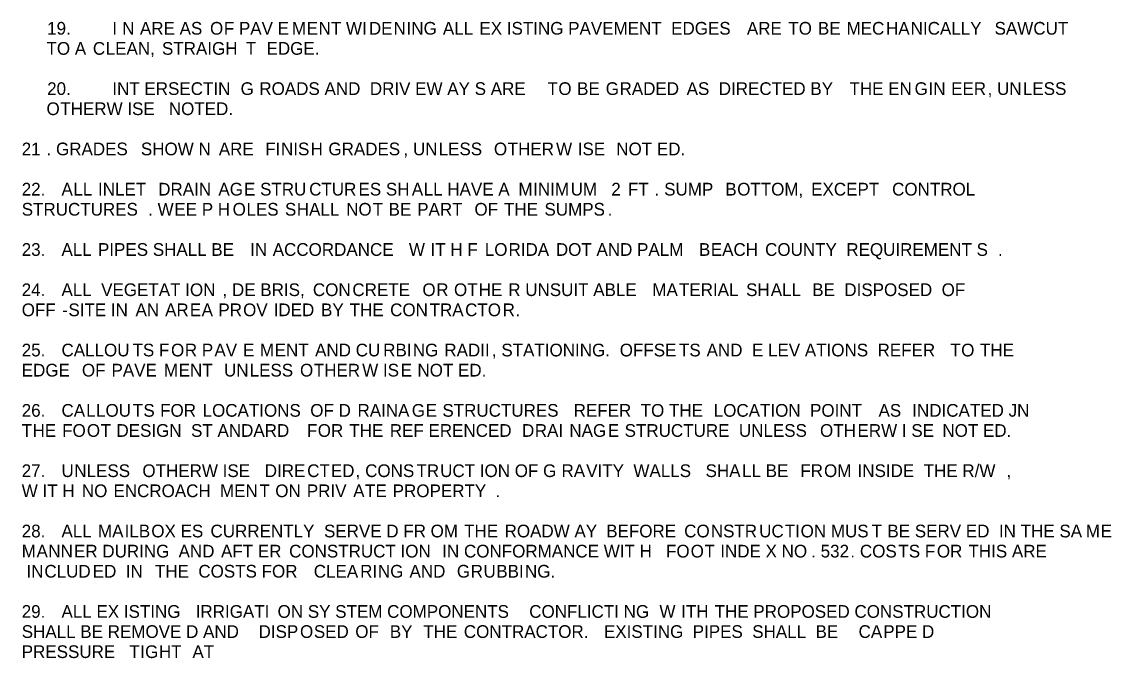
# Model space of a CAD drawing. Extents: x 783907 to 784590, y 832310 to 832609.
# Drawn here: x 783907.3 to 783958.7, y 832340.8 to 832370.9 of the extents above; entities that cross this region are included whole.
import ezdxf

# ---------------------------------------------------------------- set-up
doc = ezdxf.new("R2010")
doc.units = 0
doc.layers.add('Miscellaneous0', color=7, linetype='Continuous')

msp = doc.modelspace()

# ---------------------------------------------------------------- texts
at = {"layer": 'Miscellaneous0'}
for s, p in [('19.', (783908.482, 832370.257)), ('I ', (783911.559, 832370.257)), ('N ', (783912.024, 832370.257)), ('ARE AS ', (783912.863, 832370.257)), ('O', (783916.171, 832370.257)), ('F PAV E', (783916.823, 832370.257)), ('M', (783920.038, 832370.257)), ('E', (783920.736, 832370.257)), ('NT WI', (783921.296, 832370.257)), ('DE', (783923.67, 832370.257)), ('N', (783924.835, 832370.257)), ('I', (783925.44, 832370.257)), ('NG ', (783925.673, 832370.257)), ('ALL ', (783927.163, 832370.257)), ('EX ISTING PAVEMENT  EDGES ', (783928.887, 832370.257)), ('ARE ', (783941.513, 832370.257)), ('TO ', (783943.469, 832370.257)), ('BE ', (783944.867, 832370.257)), ('MEC', (783946.218, 832370.257)), ('HA', (783948.081, 832370.257)), ('NICALLY  ', (783949.246, 832370.257)), ('SAWCUT ', (783953.206, 832370.257)), ('TO A ', (783908.452, 832369.307)), ('C', (783910.641, 832369.307)), ('LEAN, ', (783911.246, 832369.307)), ('STRAIGH ', (783913.902, 832369.307)), ('T  ', (783917.861, 832369.307)), ('EDGE.', (783918.839, 832369.307)), ('20.', (783908.482, 832367.407)), ('INT ERSECTIN ', (783911.559, 832367.407)), ('G ', (783917.614, 832367.407)), ('ROADS AND  DRIV EW AY S ARE  ', (783918.499, 832367.407)), ('T', (783932.101, 832367.407)), ('O ', (783932.614, 832367.407)), ('BE ', (783933.499, 832367.407)), ('G', (783934.85, 832367.407)), ('RADED ', (783935.502, 832367.407)), ('AS  DIRECTED BY  ', (783938.67, 832367.407)), ('THE EN', (783946.357, 832367.407)), ('G', (783949.431, 832367.407)), ('I', (783950.083, 832367.407)), ('N ', (783950.316, 832367.407)), ('EER', (783951.154, 832367.407)), (' UN', (783953.1, 832367.407)), ('LESS ', (783954.543, 832367.407)), ('O', (783908.452, 832366.457)), ('THERW ISE  ', (783909.104, 832366.457)), ('NOTED.', (783914.227, 832366.457)), (',', (783952.878, 832367.407)), ('21 ', (783907.282, 832364.557)), ('GRADES  ', (783908.901, 832364.557)), ('SHOW N ', (783912.907, 832364.557)), ('ARE  ', (783916.586, 832364.557)), ('FI', (783918.776, 832364.557)), ('NIS', (783919.521, 832364.557)), ('H ', (783920.918, 832364.557)), ('GRADES', (783921.757, 832364.557)), ('UN', (783925.752, 832364.557)), ('LESS  ', (783926.963, 832364.557)), ('O', (783929.572, 832364.557)), ('THER', (783930.224, 832364.557)), ('W ', (783932.507, 832364.557)), ('ISE  ', (783933.531, 832364.557)), ('NOT ED.', (783935.348, 832364.557)), ('.', (783908.446, 832364.557)), (',', (783925.298, 832364.557)), ('22.', (783907.282, 832362.657)), ('A', (783909.159, 832362.657)), ('LL ', (783909.718, 832362.657)), ('INLET  ', (783910.883, 832362.657)), ('DRAIN ', (783913.724, 832362.657)), ('AG', (783916.566, 832362.657)), ('E STRU', (783917.777, 832362.657)), ('CTUR', (783920.851, 832362.657)), ('ES SH', (783923.18, 832362.657)), ('A', (783925.696, 832362.657)), ('LL HAVE A ', (783926.256, 832362.657)), ('M', (783930.729, 832362.657)), ('INIM', (783931.427, 832362.657)), ('UM   2 ', (783933.196, 832362.657)), ('FT ', (783935.897, 832362.657)), ('SUMP  ', (783937.609, 832362.657)), ('B', (783940.497, 832362.657)), ('OTTOM, ', (783941.056, 832362.657)), ('EXCEPT  ', (783944.548, 832362.657)), ('CONTROL ', (783948.369, 832362.657)), ('.', (783937.154, 832362.657)), ('STRUCTURES ', (783907.282, 832361.707)), ('W', (783913.698, 832361.707)), ('EE P H', (783914.489, 832361.707)), ('O', (783917.238, 832361.707)), ('LES ', (783917.891, 832361.707)), ('S', (783919.708, 832361.707)), ('HALL ', (783920.267, 832361.707)), ('NO', (783922.597, 832361.707)), ('T ', (783923.854, 832361.707)), ('BE ', (783924.599, 832361.707)), ('PART  ', (783925.951, 832361.707)), ('OF ', (783928.653, 832361.707)), ('THE ', (783930.05, 832361.707)), ('SUMPS', (783931.959, 832361.707)), ('.', (783913.244, 832361.707)), ('.', (783934.941, 832361.707)), ('23.', (783907.282, 832359.807)), ('ALL ', (783909.159, 832359.807)), ('PIPES SHALL BE  ', (783910.883, 832359.807)), ('I', (783918.059, 832359.807)), ('N ', (783918.291, 832359.807)), ('ACCORDANCE  ', (783919.13, 832359.807)), ('W ', (783925.558, 832359.807)), ('IT H F ', (783926.582, 832359.807)), ('LO', (783929.143, 832359.807)), ('RIDA ', (783930.261, 832359.807)), ('DOT AND PALM  ', (783932.497, 832359.807)), ('B', (783939.251, 832359.807)), ('EACH ', (783939.81, 832359.807)), ('COUNTY  REQUIREMENT S', (783942.373, 832359.807)), ('.', (783953.366, 832359.807)), ('24.', (783907.282, 832357.907)), ('ALL  VEGETAT ION', (783909.159, 832357.907)), ('DE BRIS, ', (783917.207, 832357.907)), ('CON', (783921.027, 832357.907)), ('CRETE  ', (783922.89, 832357.907)), ('O', (783926.197, 832357.907)), ('R ', (783926.849, 832357.907)), ('OT', (783927.688, 832357.907)), ('HE ', (783928.852, 832357.907)), ('R UNSUIT ABLE  ', (783930.249, 832357.907)), ('MA', (783937.051, 832357.907)), ('TERIAL ', (783938.308, 832357.907)), ('SH', (783941.476, 832357.907)), ('ALL  ', (783942.641, 832357.907)), ('BE  DISPOSED  OF  ', (783944.598, 832357.907)), (',', (783916.753, 832357.907)), ('OFF ', (783907.282, 832356.957)), ('SITE IN ', (783909.486, 832356.957)), ('AN ', (783912.654, 832356.957)), ('AR', (783914.051, 832356.957)), ('E', (783915.216, 832356.957)), ('A ', (783915.775, 832356.957)), ('PR', (783916.567, 832356.957)), ('OV ', (783917.732, 832356.957)), ('IDED ', (783919.176, 832356.957)), ('BY ', (783921.412, 832356.957)), ('THE ', (783922.763, 832356.957)), ('CON', (783924.673, 832356.957)), ('TRA', (783926.536, 832356.957)), ('CTO', (783928.213, 832356.957)), ('R', (783929.983, 832356.957)), ('-', (783909.191, 832356.957)), ('.', (783930.589, 832356.957)), ('25.', (783907.282, 832355.057)), ('CALLOU', (783909.159, 832355.057)), ('TS F', (783912.513, 832355.057)), ('O', (783914.33, 832355.057)), ('R P', (783914.982, 832355.057)), ('AV ', (783916.379, 832355.057)), ('E ', (783917.731, 832355.057)), ('M', (783918.523, 832355.057)), ('ENT ', (783919.221, 832355.057)), ('AND CU', (783921.131, 832355.057)), ('RBI', (783924.345, 832355.057)), ('NG ', (783925.742, 832355.057)), ('RADII', (783927.233, 832355.057)), ('STATIONING. ', (783929.923, 832355.057)), ('OFFSE', (783935.512, 832355.057)), ('TS ', (783938.307, 832355.057)), ('AND  E LEV ATIONS  REFER ', (783939.612, 832355.057)), ('T', (783951.118, 832355.057)), ('O ', (783951.63, 832355.057)), ('THE ', (783952.515, 832355.057)), ('EDGE  ', (783907.282, 832354.107)), ('OF ', (783910.123, 832354.107)), ('PAVE ', (783911.521, 832354.107)), ('M', (783913.991, 832354.107)), ('ENT  ', (783914.689, 832354.107)), ('UN', (783916.831, 832354.107)), ('LESS ', (783918.042, 832354.107)), ('O', (783920.419, 832354.107)), ('THER', (783921.071, 832354.107)), ('W IS', (783923.354, 832354.107)), ('E ', (783925.17, 832354.107)), ('NOT ED.', (783925.962, 832354.107)), (',', (783929.469, 832355.057)), ('26.', (783907.282, 832352.207)), ('CA', (783909.159, 832352.207)), ('L', (783910.324, 832352.207)), ('LOU', (783910.79, 832352.207)), ('T', (783912.513, 832352.207)), ('S ', (783913.025, 832352.207)), ('FOR ', (783913.817, 832352.207)), ('LOCATIONS  OF D', (783915.82, 832352.207)), ('RAINA', (783923.133, 832352.207)), ('G', (783925.695, 832352.207)), ('E ', (783926.348, 832352.207)), ('STRUCTURES  ', (783927.14, 832352.207)), ('REFER  TO THE ', (783933.335, 832352.207)), ('LOCATION  POINT  ', (783939.949, 832352.207)), ('AS  ', (783947.728, 832352.207)), ('I', (783949.312, 832352.207)), ('NDICATED JN ', (783949.544, 832352.207)), ('T', (783907.282, 832351.257)), ('HE ', (783907.794, 832351.257)), ('FO', (783909.191, 832351.257)), ('O', (783910.356, 832351.257)), ('T ', (783911.008, 832351.257)), ('DESIGN  ST ANDARD  ', (783911.753, 832351.257)), ('F', (783920.743, 832351.257)), ('OR ', (783921.255, 832351.257)), ('THE ', (783922.746, 832351.257)), ('REF ERENCED ', (783924.656, 832351.257)), ('D', (783930.898, 832351.257)), ('RAI ', (783931.503, 832351.257)), ('NAG', (783933.134, 832351.257)), ('E ', (783934.951, 832351.257)), ('STRUCTURE  UNLESS ', (783935.743, 832351.257)), ('OTH', (783944.966, 832351.257)), ('ERW I SE ', (783946.736, 832351.257)), ('NOT ED.', (783950.742, 832351.257)), ('27.', (783907.282, 832349.357)), ('U', (783909.159, 832349.357)), ('NLESS  ', (783909.764, 832349.357)), ('OTHERW ISE  ', (783912.979, 832349.357)), ('DIRE', (783918.755, 832349.357)), ('CT', (783920.758, 832349.357)), ('ED', (783921.875, 832349.357)), ('CONS', (783923.494, 832349.357)), ('TR', (783925.917, 832349.357)), ('UCT ION OF G', (783927.034, 832349.357)), ('RA', (783932.763, 832349.357)), ('VITY  WALLS  ', (783933.928, 832349.357)), ('SHA', (783939.564, 832349.357)), ('LL BE  ', (783941.288, 832349.357)), ('FR', (783944.037, 832349.357)), ('OM ', (783945.155, 832349.357)), ('INSIDE  THE R/W ', (783946.738, 832349.357)), ('W IT H ', (783907.282, 832348.407)), ('NO ', (783910.122, 832348.407)), ('ENCROACH ', (783911.612, 832348.407)), ('MEN', (783916.643, 832348.407)), ('T ', (783918.506, 832348.407)), ('ON ', (783919.251, 832348.407)), ('PRIV ', (783920.741, 832348.407)), ('A', (783922.931, 832348.407)), (',', (783923.04, 832349.357)), ('TE ', (783923.49, 832348.407)), ('PROPERTY ', (783924.795, 832348.407)), (',', (783953.771, 832349.357)), ('.', (783929.64, 832348.407)), ('28.', (783907.282, 832346.507)), ('ALL ', (783909.159, 832346.507)), ('MA', (783910.883, 832346.507)), ('ILB', (783912.141, 832346.507)), ('OX ES ', (783913.399, 832346.507)), ('CURRENTLY ', (783916.194, 832346.507)), ('SERVE D FR', (783921.551, 832346.507)), ('OM ', (783926.583, 832346.507)), ('THE ', (783928.166, 832346.507)), ('ROADW AY ', (783930.076, 832346.507)), ('BEFORE ', (783934.873, 832346.507)), ('CO', (783938.554, 832346.507)), ('NSTR', (783939.811, 832346.507)), ('UC', (783942.094, 832346.507)), ('TI', (783943.305, 832346.507)), ('ON MUS', (783944.05, 832346.507)), ('T ', (783947.403, 832346.507)), ('BE SERV ED ', (783948.148, 832346.507)), ('IN THE SA', (783953.413, 832346.507)), ('M', (783957.513, 832346.507)), ('E ', (783958.211, 832346.507)), ('M', (783907.282, 832345.557)), ('A', (783907.98, 832345.557)), ('NN', (783908.539, 832345.557)), ('ER DURING ', (783909.75, 832345.557)), ('AND ', (783914.687, 832345.557)), ('AFT ER ', (783916.691, 832345.557)), ('CONSTRUCT ION ', (783919.905, 832345.557)), ('I', (783927.124, 832345.557)), ('N CONFORMANCE WIT H ', (783927.357, 832345.557)), ('FO', (783937.696, 832345.557)), ('O', (783938.86, 832345.557)), ('T ', (783939.512, 832345.557)), ('INDE X NO', (783940.257, 832345.557)), ('532', (783944.997, 832345.557)), ('COS', (783946.849, 832345.557)), ('TS F', (783948.666, 832345.557)), ('OR ', (783950.482, 832345.557)), ('THIS ARE ', (783951.973, 832345.557)), ('.', (783944.542, 832345.557)), ('.', (783946.395, 832345.557)), (' IN', (783907.282, 832344.607)), ('CLUD', (783908.353, 832344.607)), ('ED  IN  ', (783910.635, 832344.607)), ('THE  COSTS FOR  ', (783913.569, 832344.607)), ('CLEA', (783921.068, 832344.607)), ('RI', (783923.258, 832344.607)), ('NG ', (783924.097, 832344.607)), ('AND  ', (783925.587, 832344.607)), ('G', (783927.823, 832344.607)), ('R', (783928.475, 832344.607)), ('U', (783929.081, 832344.607)), ('BBI', (783929.686, 832344.607)), ('NG.', (783931.037, 832344.607)), ('29.', (783907.282, 832342.707)), ('ALL EX ISTING  ', (783909.159, 832342.707)), ('IRRIGATI ', (783915.494, 832342.707)), ('ON SY STEM COMPONENTS  ', (783919.36, 832342.707)), ('CONFLICTI NG ', (783931.239, 832342.707)), ('W ', (783937.386, 832342.707)), ('ITH ', (783938.41, 832342.707)), ('THE PROPOSED CONSTRUCTION  ', (783939.993, 832342.707)), ('SHALL BE REMOVE D AND  ', (783907.282, 832341.757)), ('DISP', (783918.463, 832341.757)), ('O', (783920.419, 832341.757)), ('SED ', (783921.072, 832341.757)), ('OF  ', (783923.028, 832341.757)), ('BY  ', (783924.658, 832341.757)), ('THE ', (783926.242, 832341.757)), ('CONTRACTOR.  ', (783928.152, 832341.757)), ('EXISTING  PIPES  SHALL  BE  ', (783934.766, 832341.757)), ('CA', (783946.786, 832341.757)), ('PPE D ', (783947.951, 832341.757)), ('PRESSURE  ', (783907.282, 832340.807)), ('T', (783912.36, 832340.807)), ('I', (783912.872, 832340.807)), ('G', (783913.105, 832340.807)), ('HT  ', (783913.757, 832340.807)), ('AT', (783915.341, 832340.807))]:
    msp.add_text(s, height=0.6, dxfattribs=at).set_placement(p)

doc.saveas('drawing.dxf')
